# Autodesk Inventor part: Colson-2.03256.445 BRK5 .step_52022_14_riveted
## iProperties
Created: 2010-10
Part Number: Colson-2.03256.445 BRK5 .step_52022_14_riveted
Document SubType Name: Modeling
Designer: Administrator
Density: 7.85 g/cm^3
Material: Steel
Mass: 36.6099 g
Surface Area: 18.4806 cm^2
Volume: 4.66368 cm^3
Author: Administrator
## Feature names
1. Base1
